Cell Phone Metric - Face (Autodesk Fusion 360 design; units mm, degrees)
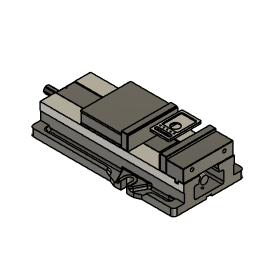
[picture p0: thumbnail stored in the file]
description: HaasClamp
derived_base_feature "Derived Base Feature" bodies "Main Body"
align "Align1"
sketch "Sketch1" plane through (0, 0, 0) normal (0, 0, -1) x axis (1, 0, 0)
  line L1 (30, 46.5) -> (30, -46.5)
  line L2 (-26.5, 50) -> (26.5, 50)
  line L3 (-30, -46.5) -> (-30, 46.5)
  line L4 (26.5, -50) -> (-26.5, -50)
  line L5 (-23.5, 38.5) -> (-23.5, 36)
  line L6 (20, 42) -> (-20, 42)
  line L7 (23.5, 36) -> (23.5, 38.5)
  line L8 (-20, 32.5) -> (20, 32.5)
  line L9 (-50.8, -55) -> (50.8, -55)
  line L10 (-50.8, 55) -> (-50.8, -55)
  line L11 (50.8, 55) -> (-50.8, 55)
  line L12 (50.8, -55) -> (50.8, 55)
  line L13 (-50.8, 55) -> (50.8, -55)
  line L14 (50.8, 55) -> (-50.8, -55)
  arc A1 centre (26.5, -46.5) radius 3.5 clockwise from (30, -46.5) to (26.5, -50)
  arc A2 centre (26.5, 46.5) radius 3.5 clockwise from (26.5, 50) to (30, 46.5)
  arc A3 centre (-26.5, 46.5) radius 3.5 clockwise from (-30, 46.5) to (-26.5, 50)
  arc A4 centre (-26.5, -46.5) radius 3.5 clockwise from (-26.5, -50) to (-30, -46.5)
  circle C1 centre (10.5, 25) radius 2.117
  circle C2 centre (-10.5, 25) radius 2.117
  circle C3 centre (-21, 25) radius 2.117
  circle C4 centre (0, 25) radius 2.117
  circle C5 centre (21, 25) radius 2.117
  arc A5 centre (-20, 38.5) radius 3.5 clockwise from (-23.5, 38.5) to (-20, 42)
  arc A6 centre (20, 38.5) radius 3.5 clockwise from (20, 42) to (23.5, 38.5)
  arc A7 centre (20, 36) radius 3.5 clockwise from (23.5, 36) to (20, 32.5)
  arc A8 centre (-20, 36) radius 3.5 clockwise from (-20, 32.5) to (-23.5, 36)
  circle C6 centre (0, 0) radius 12.5
  point P36 (0, 0)
  point P1 (0, 0)
  point P34 (-50.8, 55)
  point P35 (50.8, 55)
  point P32 (50.8, -55)
  horizontal L9
  perpendicular L9 L10
  parallel L9 L11
  parallel L10 L12
  coincident L13 P36
  coincident L14 P36
  coincident P1 P36
  dimension "d1" distance P34 P35 = 101.6
  dimension "d2" distance P32 P35 = 110
extrude "Extrude1" new body sketch "Sketch1" profile of L9 L10 L11 L12 against normal blind 6 bodies "Stock"
base_feature "Base Feature1"
base_feature "Base Feature1"
base_feature "Base Feature1"
base_feature "Base Feature1"
base_feature "Base Feature1"
base_feature "Base Feature1"
base_feature "Base Feature1"
base_feature "Base Feature1"
base_feature "Base Feature1"
base_feature "Base Feature1"
as_built_joint "As-built1"
as_built_joint "As-built2"
as_built_joint "As-built3"
joint_origin "JointOrigin1" OffsetX 0 OffsetY 0 OffsetZ 0 AngleZ 0
joint "Assemble1" alignAngle 180 alignOffsetX 0 alignOffsetY 0 alignOffsetZ 0 (= "jaw_width_haas_050002") SlideMaximum 22.5 SlideMinimum 0
position "Position1"
sketch "Sketch1" plane through (0, -72.5, 0) normal (0, -1, 0) x axis (1, 0, 0)
  line L1 (75, 73) -> (-75, 73)
  line L2 (76, 74) -> (75, 73)
  line L3 (76, 116.5) -> (76, 74)
  line L4 (75, 117.5) -> (76, 116.5)
  line L5 (-75, 117.5) -> (75, 117.5)
  line L6 (-76, 116.5) -> (-75, 117.5)
  line L7 (-76, 74) -> (-76, 116.5)
  line L8 (-75, 73) -> (-76, 74)
  line L9 (76.4, 114.275) -> (-76, 114.275)
  line L10 (76.4, 73) -> (76.4, 114.275)
  line L11 (-76, 73) -> (76.4, 73)
  line L12 (-76, 114.275) -> (-76, 73)
  circle C1 centre (49.21, 96.8) radius 11
  circle C2 centre (-49.21, 96.8) radius 11
  point P14 (76.4, 73)
  point P12 (-76, 114.275)
  point P13 (76.4, 114.275)
  horizontal L9
  vertical L10
  horizontal L11
  vertical L12
  coincident L1 P14
  coincident L7 P12
  dimension "d16" distance P12 P13 = 152.4
  dimension "d17" distance P13 P14 = 41.275
place_component sketch "Sketch1"
extrude "Extrude1" new body sketch "Sketch1" profile of L1 L2 L3 L7 L8 C1 C2 L9 L11 L12 along normal blind 3.175
place_component sketch "Sketch1"
extrude "Extrude1" sketch "Sketch1" profile of L1 L2 L3 L7 L8 C1 C2 L9 L11 L12 blind -3.175
as_built_joint "As-built5"
as_built_joint "As-built6"
position "Position1"
ground "Pin"
position "Position2"
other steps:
create_component "CreateComponent1"
create_component "CreateComponent2"
create_component "CreateComponent3"
create_component "CreateComponent4"
create_component "CreateComponent5"
create_component "CreateComponent6"
create_component "CreateComponent7"
create_component "CreateComponent8"
create_component "CreateComponent9"
create_component "CreateComponent10"
joint_origin "JointOrigin10"
joint_origin "JointOrigin11"
create_component "CreateComponent11" sketch "Sketch1"
create_component "CreateComponent12" sketch "Sketch1"
create_component "CreateComponent1"
named bodies: "Main Body", "Stock"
